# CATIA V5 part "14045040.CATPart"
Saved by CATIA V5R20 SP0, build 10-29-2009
Part number: 14045040
Definition: NONE
Nomenclature: 14045040
Source: Unknown
Description: 14045040
Bounding box of the stored display mesh (mm): x -20 to 80, y -36.5 to 26.406, z -26.6 to 26.6
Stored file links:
  C:\Users\Utente\Desktop\IO LAVORO\3D X SITO CF\X SITO\PLASTICA\RF2\14045040.CATPart
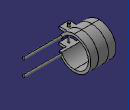
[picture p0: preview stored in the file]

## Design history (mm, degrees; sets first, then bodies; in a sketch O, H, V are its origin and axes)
Body1 "14045040" (main body)
  Solid1: solid without history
